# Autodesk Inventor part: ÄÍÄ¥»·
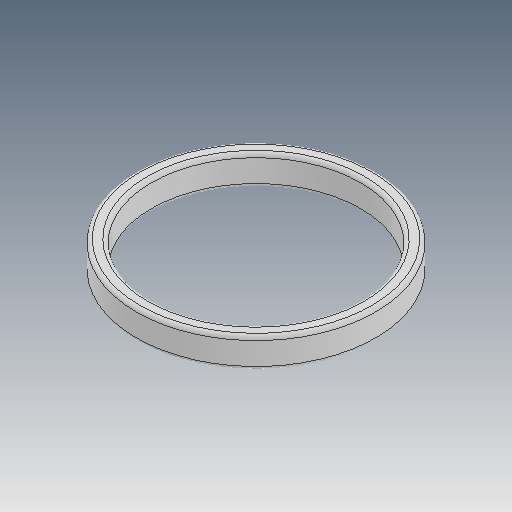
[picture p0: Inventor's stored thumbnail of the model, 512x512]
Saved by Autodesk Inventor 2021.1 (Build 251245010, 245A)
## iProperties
Created: 2013-04
Part Number: ÄÍÄ¥»·
Material: Ogólny
Document SubType Name: Modeling
Designer: user
Density: 1 g/cm^3
Appearance: Domyślna
Author: user
Revision Number: ÈÎºÎ
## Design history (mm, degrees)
feature "Ô²½Ç1"
node "Bryła1"
